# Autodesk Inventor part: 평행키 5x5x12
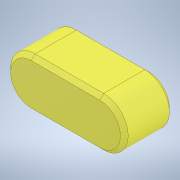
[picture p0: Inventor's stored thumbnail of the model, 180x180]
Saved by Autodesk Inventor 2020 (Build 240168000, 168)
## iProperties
Created: 2024-04
Part Number: 평행키 5x5x12
Material: 강철, 연강
Description: 키 및 해당 키홈
Document SubType Name: Modeling
Designer: oem
Density: 7.85 g/cm^3
Appearance: 기본값
Author: jhkim
Sending System: Autodesk Inventor 2025
Preprocessor: ST-DEVELOPER v20
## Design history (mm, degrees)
feature "Solid1"
node "솔리드1"
